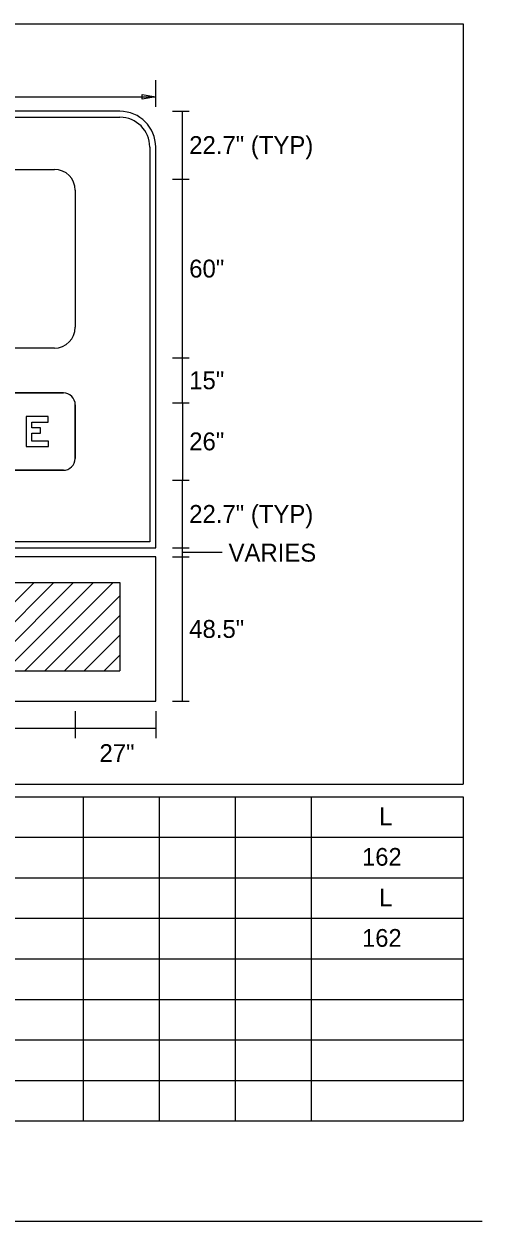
# Model space of a CAD drawing. Extents: x 10268312 to 10268706, y 2142548 to 2142786.
# Drawn here: x 10268453.64 to 10268471.73, y 2142640.28 to 2142687.53 of the extents above; entities that cross this region are included whole.
import ezdxf

# ---------------------------------------------------------------- set-up
doc = ezdxf.new("R2010")
doc.units = 0
for name, color, linetype in [('GSBWFill', 7, 'Continuous'), ('GSDims', 7, 'Continuous'), ('SheetBorder_dp', 7, 'Continuous'), ('SignPanel', 7, 'Continuous'), ('SumBoxLines_dp', 7, 'Continuous'), ('SumBoxLinesMin_dp', 7, 'Continuous'), ('TextLabel', 7, 'Continuous'), ('TextMisc', 7, 'Continuous')]:
    doc.layers.add(name, color=color, linetype=linetype)

msp = doc.modelspace()

# ---------------------------------------------------------------- linework, layer by layer
at = {"layer": 'GSBWFill'}
for p, q in [((10268458.845, 2142684.26), (10268458.845, 2142685.318)), ((10268457.434, 2142684.084), (10268434.856, 2142684.084)), ((10268434.856, 2142683.849), (10268457.434, 2142683.849)), ((10268458.61, 2142682.673), (10268458.61, 2142667.092)), ((10268437.092, 2142672.972), (10268455.198, 2142672.972)), ((10268437.092, 2142672.972), (10268455.198, 2142672.972)), ((10268455.668, 2142672.501), (10268455.668, 2142670.384)), ((10268455.668, 2142672.501), (10268455.668, 2142670.384)), ((10268455.198, 2142669.914), (10268437.092, 2142669.914)), ((10268455.198, 2142669.914), (10268437.092, 2142669.914))]:
    msp.add_line(p, q, dxfattribs=at)
msp.add_lwpolyline([(10268458.61, 2142667.092), (10268433.687, 2142667.092), (10268433.687, 2142666.857), (10268458.845, 2142666.857), (10268458.845, 2142666.857), (10268458.845, 2142682.673)], dxfattribs=at)
for centre, radius, start, end in [((10268457.434, 2142682.673), 1.411, 0, 90), ((10268457.434, 2142682.673), 1.176, 0, 90), ((10268455.198, 2142672.501), 0.47, 0, 90), ((10268455.198, 2142672.501), 0.47, 0, 90), ((10268455.193, 2142670.384), 0.47, 270, 0), ((10268455.193, 2142670.384), 0.47, 270, 0)]:
    msp.add_arc(centre, radius, start, end, dxfattribs=at)
at = {"layer": 'GSDims'}
for p, q in [((10268433.445, 2142684.657), (10268458.845, 2142684.657)), ((10268459.507, 2142684.084), (10268460.168, 2142684.084)), ((10268459.904, 2142681.415), (10268459.904, 2142684.084)), ((10268460.168, 2142684.084), (10268460.168, 2142684.084)), ((10268459.507, 2142681.403), (10268460.168, 2142681.403)), ((10268459.904, 2142674.349), (10268459.904, 2142681.415)), ((10268459.507, 2142674.349), (10268460.168, 2142674.349)), ((10268459.904, 2142672.584), (10268459.904, 2142674.349)), ((10268459.507, 2142672.583), (10268460.168, 2142672.583)), ((10268459.904, 2142672.583), (10268459.904, 2142669.526)), ((10268459.507, 2142669.526), (10268460.168, 2142669.526)), ((10268459.904, 2142666.857), (10268459.904, 2142669.526)), ((10268459.507, 2142666.857), (10268460.168, 2142666.857)), ((10268459.904, 2142666.504), (10268459.904, 2142666.857)), ((10268459.904, 2142666.68), (10268461.464, 2142666.68)), ((10268459.507, 2142666.504), (10268460.168, 2142666.504)), ((10268459.904, 2142660.8), (10268459.904, 2142666.504)), ((10268459.507, 2142660.8), (10268460.168, 2142660.8)), ((10268455.67, 2142660.403), (10268455.67, 2142659.345)), ((10268458.845, 2142660.403), (10268458.845, 2142659.345)), ((10268436.62, 2142659.742), (10268455.67, 2142659.742)), ((10268455.67, 2142659.742), (10268458.845, 2142659.742))]:
    msp.add_line(p, q, dxfattribs=at)
msp.add_lwpolyline([(10268458.845, 2142684.657), (10268458.316, 2142684.569), (10268458.316, 2142684.745)], close=True, dxfattribs=at)
at = {"layer": 'SheetBorder_dp'}
msp.add_line((10268317.73, 2142640.282), (10268471.73, 2142640.282), dxfattribs=at)
at = {"layer": 'SignPanel'}
for p, q in [((10268437.445, 2142681.791), (10268454.845, 2142681.791)), ((10268455.668, 2142680.968), (10268455.668, 2142675.56)), ((10268454.845, 2142674.737), (10268437.445, 2142674.737)), ((10268455.198, 2142672.972), (10268437.092, 2142672.972)), ((10268455.664, 2142670.384), (10268455.668, 2142672.501)), ((10268437.092, 2142669.914), (10268455.193, 2142669.914)), ((10268458.845, 2142666.504), (10268433.445, 2142666.504)), ((10268458.845, 2142660.8), (10268458.845, 2142666.504)), ((10268433.445, 2142660.8), (10268458.845, 2142660.8))]:
    msp.add_line(p, q, dxfattribs=at)
msp.add_lwpolyline([(10268454.618, 2142671.066), (10268453.948, 2142671.066), (10268453.948, 2142671.383), (10268454.294, 2142671.383), (10268454.294, 2142671.594), (10268453.948, 2142671.594), (10268453.948, 2142671.819), (10268454.6, 2142671.819), (10268454.6, 2142672.031), (10268453.736, 2142672.031), (10268453.736, 2142670.855), (10268454.618, 2142670.855)], close=True, dxfattribs=at)
msp.add_lwpolyline([(10268454.618, 2142671.066), (10268453.948, 2142671.066), (10268453.948, 2142671.383), (10268454.294, 2142671.383), (10268454.294, 2142671.594), (10268453.948, 2142671.594), (10268453.948, 2142671.819), (10268454.6, 2142671.819), (10268454.6, 2142672.031), (10268453.736, 2142672.031), (10268453.736, 2142670.855), (10268454.618, 2142670.855)], close=True, dxfattribs=at)
msp.add_lwpolyline([(10268454.618, 2142671.066), (10268453.948, 2142671.066), (10268453.948, 2142671.383), (10268454.294, 2142671.383), (10268454.294, 2142671.594), (10268453.948, 2142671.594), (10268453.948, 2142671.819), (10268454.6, 2142671.819), (10268454.6, 2142672.031), (10268453.736, 2142672.031), (10268453.736, 2142670.855), (10268454.618, 2142670.855)], close=True, dxfattribs=at)
for centre, radius, start, end in [((10268454.845, 2142680.968), 0.823, 0, 90), ((10268454.845, 2142675.56), 0.823, 270, 360), ((10268455.198, 2142672.501), 0.47, 0, 90), ((10268455.193, 2142670.384), 0.47, 270, 0)]:
    msp.add_arc(centre, radius, start, end, dxfattribs=at)
at = {"layer": 'SumBoxLines_dp'}
for p, q in [((10268418.73, 2142687.532), (10268470.98, 2142687.532)), ((10268470.98, 2142687.532), (10268470.98, 2142657.532)), ((10268418.73, 2142657.532), (10268470.98, 2142657.532)), ((10268395.48, 2142657.032), (10268470.98, 2142657.032)), ((10268455.98, 2142657.032), (10268455.98, 2142655.432)), ((10268458.98, 2142657.032), (10268458.98, 2142655.432)), ((10268461.98, 2142657.032), (10268461.98, 2142655.432)), ((10268464.98, 2142657.032), (10268464.98, 2142655.432)), ((10268470.98, 2142657.032), (10268470.98, 2142644.232)), ((10268455.98, 2142655.432), (10268455.98, 2142649.032)), ((10268458.98, 2142655.432), (10268458.98, 2142649.032)), ((10268461.98, 2142655.432), (10268461.98, 2142649.032)), ((10268464.98, 2142655.432), (10268464.98, 2142644.232)), ((10268395.48, 2142653.832), (10268470.98, 2142653.832)), ((10268395.48, 2142650.632), (10268470.98, 2142650.632)), ((10268455.98, 2142649.032), (10268455.98, 2142644.232)), ((10268458.98, 2142649.032), (10268458.98, 2142644.232)), ((10268461.98, 2142649.032), (10268461.98, 2142644.232)), ((10268395.48, 2142647.432), (10268470.98, 2142647.432)), ((10268395.48, 2142644.232), (10268470.98, 2142644.232))]:
    msp.add_line(p, q, dxfattribs=at)
at = {"layer": 'SumBoxLinesMin_dp'}
for p, q in [((10268395.48, 2142655.432), (10268470.98, 2142655.432)), ((10268395.48, 2142652.232), (10268470.98, 2142652.232)), ((10268395.48, 2142649.032), (10268470.98, 2142649.032)), ((10268395.48, 2142645.832), (10268470.98, 2142645.832))]:
    msp.add_line(p, q, dxfattribs=at)
at = {"layer": 'TextMisc'}
for p, q in [((10268434.856, 2142665.482), (10268457.434, 2142665.482)), ((10268450.55, 2142661.998), (10268454.041, 2142665.482)), ((10268451.332, 2142661.998), (10268454.823, 2142665.482)), ((10268452.115, 2142661.998), (10268455.605, 2142665.482)), ((10268452.897, 2142661.998), (10268456.388, 2142665.482)), ((10268453.679, 2142661.998), (10268457.17, 2142665.482)), ((10268457.434, 2142665.482), (10268457.434, 2142661.998)), ((10268454.462, 2142661.998), (10268457.434, 2142664.965)), ((10268455.244, 2142661.998), (10268457.434, 2142664.184)), ((10268456.026, 2142661.998), (10268457.434, 2142663.403)), ((10268456.809, 2142661.998), (10268457.434, 2142662.623)), ((10268434.856, 2142661.998), (10268457.434, 2142661.998))]:
    msp.add_line(p, q, dxfattribs=at)

# ---------------------------------------------------------------- texts
at = {"layer": 'GSDims'}
for s, height, p in [('22.7" (TYP)', 0.70558, (10268460.168, 2142682.397)), ('60"', 0.7056, (10268460.168, 2142677.523)), ('15"', 0.7056, (10268460.168, 2142673.114)), ('26"', 0.7056, (10268460.168, 2142670.702)), ('22.7" (TYP)', 0.70558, (10268460.168, 2142667.838)), ('VARIES', 0.7056, (10268461.721, 2142666.31)), ('48.5"', 0.7056, (10268460.168, 2142663.299)), ('27"', 0.7056, (10268456.625, 2142658.398))]:
    msp.add_text(s, height=height, dxfattribs=at).set_placement(p)
at = {"layer": 'TextLabel'}
for s, p in [('L', (10268467.668, 2142655.907)), ('162', (10268466.993, 2142654.307)), ('L', (10268467.668, 2142652.707)), ('162', (10268466.993, 2142651.107))]:
    msp.add_text(s, height=0.7, dxfattribs=at).set_placement(p)

doc.saveas('drawing.dxf')
